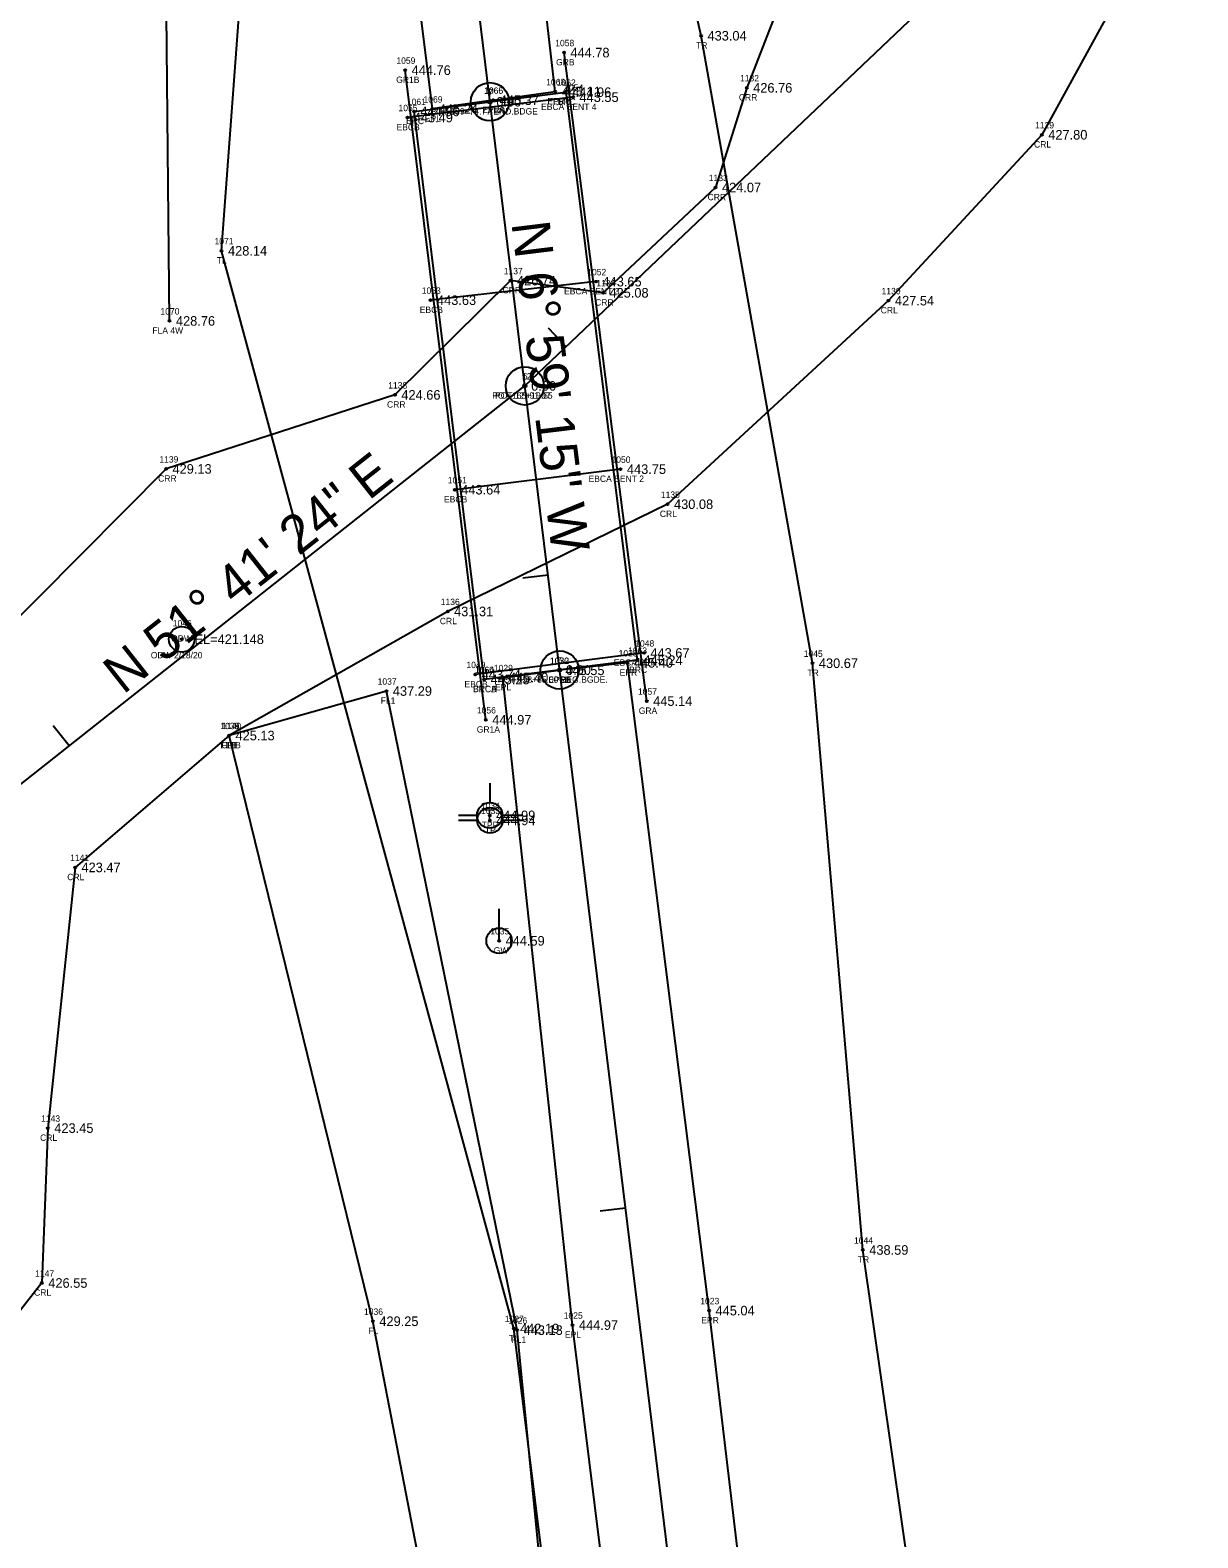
# Model space of a CAD drawing. Extents: x 1858454 to 1858924, y 1147053 to 1148170.
# Drawn here: x 1858606.4 to 1858789.5, y 1147434.7 to 1147671.2 of the extents above; entities that cross this region are included whole.
import ezdxf

# ---------------------------------------------------------------- set-up
doc = ezdxf.new("R2010")
doc.units = 0
for name, color, linetype in [('RD_EX_Bridge', 7, 'Continuous'), ('RD_EX_Bridge_txCode', 7, 'Continuous'), ('RD_EX_Fence_Other', 7, 'Continuous'), ('RD_EX_Fence_Other_txCode', 7, 'Continuous'), ('RD_EX_GuardRail', 7, 'Continuous'), ('RD_EX_GuardRail_txCode', 7, 'Continuous'), ('RD_EX_H2O', 7, 'Continuous'), ('RD_EX_H2O_txCode', 7, 'Continuous'), ('RD_EX_Road', 7, 'Continuous'), ('RD_EX_Road_txCode', 7, 'Continuous'), ('RD_EX_TX_Bridge_ELEV', 7, 'Continuous'), ('RD_EX_TX_Fence_Other_ELEV', 7, 'Continuous'), ('RD_EX_TX_GuardRail_ELEV', 7, 'Continuous'), ('RD_EX_TX_H2O_ELEV', 7, 'Continuous'), ('RD_EX_TX_Road_ELEV', 7, 'Continuous'), ('RD_EX_TX_UT_ELEV', 7, 'Continuous'), ('RD_EX_TX_VEG_ELEV', 7, 'Continuous'), ('RD_EX_UT', 7, 'Continuous'), ('RD_EX_UT_txCode', 7, 'Continuous'), ('RD_EX_VEG', 7, 'Continuous'), ('RD_EX_VEG_txCode', 7, 'Continuous'), ('RD_HC_Cl', 7, 'Continuous'), ('RD_HC_Data', 7, 'Continuous'), ('RD_HC_Data_Tic', 7, 'Continuous'), ('RD_HC_Survey_ELEV', 7, 'Continuous'), ('RD_HC_txCode', 7, 'Continuous'), ('RD_SMD_Locator', 7, 'Continuous')]:
    doc.layers.add(name, color=color, linetype=linetype)

msp = doc.modelspace()

# ---------------------------------------------------------------- linework, layer by layer
at = {"layer": 'RD_EX_Bridge'}
for p, q in [((1858691.53, 1147660.66), (1858665.55, 1147657.47)), ((1858695.14, 1147631.74), (1858669.19, 1147628.83)), ((1858698.97, 1147602.33), (1858672.99, 1147599.11)), ((1858702.65, 1147573.51), (1858676.2, 1147570.13))]:
    msp.add_line(p, q, dxfattribs=at)
msp.add_lwpolyline([(1858677.59, 1147569.36), (1858666.6, 1147658.44), (1858690.38, 1147661.45), (1858701.56, 1147572.37), (1858677.59, 1147569.35)], dxfattribs=at)
at = {"layer": 'RD_EX_Fence_Other'}
for points in [[(1858628.27, 1147625.58), (1858627.01, 1147754.05), (1858615.95, 1147851.08), (1858606.98, 1147957.76), (1858595.17, 1148052.68), (1858581.78, 1148154.12)], [(1858680.85, 1147361.22), (1858692.48, 1147368.01), (1858682.77, 1147467.32), (1858662.27, 1147567.54), (1858637.61, 1147560.56)], [(1858724.59, 1147070.61), (1858704.63, 1147165.53), (1858685.01, 1147263.02), (1858674.78, 1147319.72), (1858680.95, 1147360.94), (1858660.16, 1147468.71), (1858637.61, 1147560.56)]]:
    msp.add_lwpolyline(points, dxfattribs=at)
at = {"layer": 'RD_EX_GuardRail'}
for p, q in [((1858703.08, 1147565.96), (1858690.11, 1147667.66)), ((1858677.86, 1147563.02), (1858665.22, 1147664.9))]:
    msp.add_line(p, q, dxfattribs=at)
at = {"layer": 'RD_EX_H2O'}
for points in [[(1858879.83, 1148102.54), (1858871.42, 1148034.27), (1858866.93, 1147971.73), (1858863.21, 1147909.44), (1858860.9, 1147860.04), (1858873.82, 1147825.54), (1858891.79, 1147781.55), (1858894.95, 1147773.07), (1858887.01, 1147735.25), (1858825.08, 1147733.03), (1858791.14, 1147702.41), (1858765.02, 1147654.77), (1858740.99, 1147628.76), (1858706.35, 1147596.83), (1858671.87, 1147580.02), (1858637.61, 1147560.56), (1858613.46, 1147539.88), (1858609.2, 1147499), (1858608.26, 1147474.71), (1858583.43, 1147442.99), (1858542.68, 1147417.32), (1858497.34, 1147430.55)], [(1858842, 1147848.22), (1858847.52, 1147794.04), (1858841.16, 1147786.48), (1858816.23, 1147769.28), (1858759.58, 1147742.8), (1858751.47, 1147732.35), (1858731.2, 1147689.66), (1858724.77, 1147677.64), (1858718.76, 1147662.14), (1858713.87, 1147646.5), (1858696.23, 1147629.99), (1858681.73, 1147631.9), (1858663.61, 1147613.98), (1858627.73, 1147602.37), (1858587.46, 1147561.81), (1858570.79, 1147529.07), (1858577.35, 1147512.16), (1858564.18, 1147528.65), (1858536.5, 1147564.8), (1858503.8, 1147609.24)]]:
    msp.add_lwpolyline(points, dxfattribs=at)
for radius in [2, 0.15]:
    msp.add_circle((1858630.18, 1147575.66), radius, dxfattribs=at)
at = {"layer": 'RD_EX_Road'}
for points in [[(1858679.02, 1147660.19), (1858688.73, 1147661.54), (1858677.21, 1147761.6), (1858664.75, 1147860.38), (1858652.33, 1147959.9), (1858640.18, 1148058.71), (1858627.63, 1148158.94)], [(1858679.02, 1147660.19), (1858669.49, 1147658.82), (1858657, 1147758.92), (1858643.96, 1147857.84), (1858631.87, 1147958), (1858619.69, 1148055.49), (1858606.59, 1148156.75)], [(1858739.58, 1147072.32), (1858726.74, 1147170.58), (1858715.7, 1147269.68), (1858703.76, 1147368.69), (1858691.45, 1147468.11), (1858680.5, 1147569.65), (1858689.32, 1147570.79)], [(1858760.33, 1147074.17), (1858747.61, 1147172.63), (1858736.08, 1147271.97), (1858724.51, 1147372.2), (1858712.86, 1147470.38), (1858700.06, 1147571.96), (1858689.32, 1147570.79)]]:
    msp.add_lwpolyline(points, dxfattribs=at)
at = {"layer": 'RD_EX_UT'}
for p, q in [((1858678.47, 1147553.11), (1858678.47, 1147550.04)), ((1858673.54, 1147548.06), (1858676.47, 1147548.06)), ((1858673.57, 1147547.27), (1858676.5, 1147547.27)), ((1858680.47, 1147548.06), (1858683.54, 1147548.06)), ((1858680.5, 1147547.27), (1858683.57, 1147547.27)), ((1858679.94, 1147528.37), (1858679.94, 1147533.37))]:
    msp.add_line(p, q, dxfattribs=at)
for centre in [(1858678.47, 1147548.04), (1858678.5, 1147547.25), (1858679.94, 1147528.37)]:
    msp.add_circle(centre, 2, dxfattribs=at)
at = {"layer": 'RD_EX_VEG'}
for points in [[(1858786.58, 1147073.62), (1858775.98, 1147174.64), (1858762.89, 1147274.03), (1858752.24, 1147373.24), (1858736.96, 1147479.89), (1858729.06, 1147571.9), (1858711.6, 1147670.3), (1858690.41, 1147764.38), (1858680.89, 1147862.43), (1858668.42, 1147961.01), (1858651.26, 1148061.01), (1858641.53, 1148160.37)], [(1858726.29, 1147071.02), (1858708.41, 1147166.41), (1858698.92, 1147264.27), (1858694.52, 1147368.74), (1858682.22, 1147467.57), (1858636.43, 1147636.58), (1858645.41, 1147757.54), (1858631.11, 1147856.08), (1858618.46, 1147956.68), (1858606.82, 1148055.62), (1858592.91, 1148154.69)]]:
    msp.add_lwpolyline(points, dxfattribs=at)
at = {"layer": 'RD_HC_Cl'}
for p, q in [((1858750.25, 1147074.55), (1858617.68, 1148156.23)), ((1858683.96, 1147615.39), (1858865, 1147787.44)), ((1858601.42, 1147550.17), (1858683.96, 1147615.39))]:
    msp.add_line(p, q, dxfattribs=at)
at = {"layer": 'RD_HC_Data'}
for centre, radius in [((1858678.5, 1147659.95), 3), ((1858678.5, 1147659.95), 0.282), ((1858683.96, 1147615.39), 3), ((1858683.96, 1147615.39), 3), ((1858683.96, 1147615.39), 0.282), ((1858683.96, 1147615.39), 0.282), ((1858689.42, 1147570.84), 3), ((1858689.42, 1147570.84), 0.282)]:
    msp.add_circle(centre, radius, dxfattribs=at)
at = {"layer": 'RD_HC_Data_Tic'}
for p, q in [((1858690.44, 1147621.54), (1858687.68, 1147624.44)), ((1858687.6, 1147585.73), (1858683.63, 1147585.24)), ((1858612.51, 1147558.93), (1858610.03, 1147562.07)), ((1858699.77, 1147486.47), (1858695.8, 1147485.98))]:
    msp.add_line(p, q, dxfattribs=at)
at = {"layer": 'RD_SMD_Locator'}
for centre in [(1858711.6, 1147670.3), (1858690.11, 1147667.66), (1858665.22, 1147664.9), (1858718.76, 1147662.14), (1858678.5, 1147659.95), (1858679.02, 1147660.19), (1858679.02, 1147660.19), (1858688.73, 1147661.54), (1858690.38, 1147661.45), (1858691.53, 1147660.66), (1858665.55, 1147657.47), (1858666.6, 1147658.44), (1858669.49, 1147658.82), (1858765.02, 1147654.77), (1858713.87, 1147646.5), (1858636.43, 1147636.58), (1858681.73, 1147631.9), (1858695.14, 1147631.74), (1858669.19, 1147628.83), (1858696.23, 1147629.99), (1858740.99, 1147628.76), (1858628.27, 1147625.58), (1858683.96, 1147615.39), (1858683.96, 1147615.39), (1858663.61, 1147613.98), (1858627.73, 1147602.37), (1858698.97, 1147602.33), (1858672.99, 1147599.11), (1858706.35, 1147596.83), (1858671.87, 1147580.02), (1858700.06, 1147571.96), (1858701.56, 1147572.37), (1858702.65, 1147573.51), (1858676.2, 1147570.13), (1858680.5, 1147569.65), (1858689.32, 1147570.79), (1858689.32, 1147570.79), (1858689.42, 1147570.84), (1858729.06, 1147571.9), (1858662.27, 1147567.54), (1858677.59, 1147569.36), (1858677.59, 1147569.35), (1858703.08, 1147565.96), (1858677.86, 1147563.02), (1858637.61, 1147560.56), (1858637.61, 1147560.56), (1858637.61, 1147560.56), (1858678.47, 1147548.04), (1858678.5, 1147547.25), (1858613.46, 1147539.88), (1858679.94, 1147528.37), (1858609.2, 1147499), (1858736.96, 1147479.89), (1858608.26, 1147474.71), (1858712.86, 1147470.38), (1858660.16, 1147468.71), (1858691.45, 1147468.11), (1858682.22, 1147467.57), (1858682.77, 1147467.32)]:
    msp.add_circle(centre, 0.15, dxfattribs=at)

# ---------------------------------------------------------------- texts
at = {"layer": 'RD_EX_Bridge_txCode'}
for s, p in [('1062', (1858688.97, 1147662.45)), ('1054', (1858690.15, 1147661.66)), ('1061', (1858665.47, 1147659.44)), ('EBCA BENT 4', (1858686.51, 1147658.66)), ('BRC', (1858689.13, 1147659.45)), ('1055', (1858664.16, 1147658.47)), ('BRC', (1858665.35, 1147656.44)), ('EBCB', (1858663.85, 1147655.47)), ('1052', (1858693.75, 1147632.74)), ('1053', (1858667.81, 1147629.83)), ('EBCA BENT 3', (1858690.11, 1147629.74)), ('EBCB', (1858667.49, 1147626.83)), ('1050', (1858697.55, 1147603.33)), ('1051', (1858671.89, 1147600.11)), ('EBCA BENT 2', (1858693.95, 1147600.33)), ('EBCB', (1858671.29, 1147597.11)), ('1048', (1858701.27, 1147574.51)), ('1049', (1858674.81, 1147571.13)), ('EBCA BENT 1', (1858697.91, 1147571.51)), ('1063', (1858700.15, 1147573.37)), ('1060', (1858676.14, 1147570.36)), ('1064', (1858676.18, 1147570.35)), ('BRC', (1858700.31, 1147570.37)), ('EBCB', (1858674.5, 1147568.13)), ('BRCA', (1858675.85, 1147567.36)), ('BRCB', (1858675.86, 1147567.35))]:
    msp.add_text(s, height=1, dxfattribs=at).set_placement(p)
at = {"layer": 'RD_EX_Fence_Other_txCode'}
for s, p in [('1070', (1858626.84, 1147626.58)), ('FLA 4W', (1858625.57, 1147623.58)), ('1037', (1858660.89, 1147568.54)), ('FL1', (1858661.37, 1147565.54)), ('1038', (1858636.23, 1147561.56)), ('1039', (1858636.23, 1147561.56)), ('FL1B', (1858636.24, 1147558.56)), ('FLB', (1858636.41, 1147558.56)), ('1036', (1858658.75, 1147469.71)), ('1026', (1858681.36, 1147468.32)), ('FL', (1858659.43, 1147466.71)), ('FL1', (1858681.87, 1147465.32))]:
    msp.add_text(s, height=1, dxfattribs=at).set_placement(p)
at = {"layer": 'RD_EX_GuardRail_txCode'}
for s, p in [('1058', (1858688.73, 1147668.66)), ('1059', (1858663.83, 1147665.9)), ('GRB', (1858688.86, 1147665.66)), ('GR1B', (1858663.8, 1147662.9)), ('1057', (1858701.7, 1147566.96)), ('1056', (1858676.45, 1147564.02)), ('GRA', (1858701.82, 1147563.96)), ('GR1A', (1858676.43, 1147561.02))]:
    msp.add_text(s, height=1, dxfattribs=at).set_placement(p)
at = {"layer": 'RD_EX_H2O'}
msp.add_text('ODW', height=1, dxfattribs=at).set_placement((1858628.51, 1147575.29))
at = {"layer": 'RD_EX_H2O_txCode'}
for s, p in [('1132', (1858717.7, 1147663.14)), ('CRR', (1858717.51, 1147660.14)), ('1129', (1858763.95, 1147655.77)), ('CRL', (1858763.79, 1147652.77)), ('1133', (1858712.81, 1147647.5)), ('CRR', (1858712.62, 1147644.5)), ('1137', (1858680.66, 1147632.9)), ('1134', (1858695.17, 1147630.99)), ('CRR', (1858680.47, 1147629.9)), ('CRR', (1858694.98, 1147627.99)), ('1130', (1858739.89, 1147629.76)), ('CRL', (1858739.76, 1147626.76)), ('1138', (1858662.55, 1147614.98)), ('CRR', (1858662.36, 1147611.98)), ('1139', (1858626.67, 1147603.37)), ('CRR', (1858626.48, 1147600.37)), ('1135', (1858705.29, 1147597.83)), ('CRL', (1858705.13, 1147594.83)), ('1136', (1858670.78, 1147581.02)), ('1046', (1858628.77, 1147577.66)), ('CRL', (1858670.64, 1147578.02)), ('ODW 2/18/20', (1858625.33, 1147572.66)), ('1140', (1858636.51, 1147561.56)), ('CRL', (1858636.39, 1147558.56)), ('1141', (1858612.68, 1147540.88)), ('CRL', (1858612.23, 1147537.88)), ('1143', (1858608.13, 1147500)), ('CRL', (1858607.97, 1147497)), ('1147', (1858607.2, 1147475.71)), ('CRL', (1858607.03, 1147472.71))]:
    msp.add_text(s, height=1, dxfattribs=at).set_placement(p)
at = {"layer": 'RD_EX_Road_txCode'}
for s, p in [('1066', (1858677.58, 1147661.19)), ('1065', (1858677.61, 1147661.19)), ('1068', (1858687.32, 1147662.54)), ('1069', (1858668.08, 1147659.82)), ('EPR', (1858687.5, 1147659.54)), ('EPL', (1858668.28, 1147656.82)), ('EPRA', (1858677.3, 1147658.19)), ('EPLA', (1858677.32, 1147658.19)), ('1030', (1858687.89, 1147571.79)), ('1032', (1858687.93, 1147571.79)), ('1028', (1858698.67, 1147572.96)), ('1029', (1858679.11, 1147570.65)), ('EPRB', (1858687.62, 1147568.79)), ('EPLB', (1858687.64, 1147568.79)), ('EPR', (1858698.83, 1147569.96)), ('EPL', (1858679.29, 1147567.65)), ('1023', (1858711.47, 1147471.38)), ('1025', (1858690.06, 1147469.11)), ('EPR', (1858711.63, 1147468.38)), ('EPL', (1858690.25, 1147466.11))]:
    msp.add_text(s, height=1, dxfattribs=at).set_placement(p)
at = {"layer": 'RD_EX_TX_Bridge_ELEV'}
for s, p in [('444.96', (1858691.38, 1147660.7)), ('443.55', (1858692.53, 1147659.91)), ('443.49', (1858666.55, 1147656.72)), ('444.96', (1858667.6, 1147657.69)), ('443.65', (1858696.14, 1147630.99)), ('443.63', (1858670.19, 1147628.08)), ('443.75', (1858699.97, 1147601.58)), ('443.64', (1858673.99, 1147598.36)), ('445.24', (1858702.56, 1147571.62)), ('443.67', (1858703.65, 1147572.76)), ('443.74', (1858677.2, 1147569.38)), ('445.25', (1858678.59, 1147568.61)), ('445.25', (1858678.59, 1147568.6))]:
    msp.add_text(s, height=1.5, dxfattribs=at).set_placement(p)
at = {"layer": 'RD_EX_TX_Fence_Other_ELEV'}
for s, p in [('428.76', (1858629.27, 1147624.83)), ('437.29', (1858663.27, 1147566.79)), ('425.13', (1858638.61, 1147559.81)), ('425.13', (1858638.61, 1147559.81)), ('429.25', (1858661.16, 1147467.96)), ('443.13', (1858683.77, 1147466.57))]:
    msp.add_text(s, height=1.5, dxfattribs=at).set_placement(p)
at = {"layer": 'RD_EX_TX_GuardRail_ELEV'}
for s, p in [('444.78', (1858691.11, 1147666.91)), ('444.76', (1858666.22, 1147664.15)), ('445.14', (1858704.08, 1147565.21)), ('444.97', (1858678.86, 1147562.27))]:
    msp.add_text(s, height=1.5, dxfattribs=at).set_placement(p)
at = {"layer": 'RD_EX_TX_H2O_ELEV'}
for s, p in [('426.76', (1858719.76, 1147661.39)), ('427.80', (1858766.02, 1147654.02)), ('424.07', (1858714.87, 1147645.75)), ('426.74', (1858682.73, 1147631.15)), ('425.08', (1858697.23, 1147629.24)), ('427.54', (1858741.99, 1147628.01)), ('424.66', (1858664.61, 1147613.23)), ('429.13', (1858628.73, 1147601.62)), ('430.08', (1858707.35, 1147596.08)), ('431.31', (1858672.87, 1147579.27)), ('EL=421.148', (1858632.18, 1147574.91)), ('425.13', (1858638.61, 1147559.81)), ('423.47', (1858614.46, 1147539.13)), ('423.45', (1858610.2, 1147498.25)), ('426.55', (1858609.26, 1147473.96))]:
    msp.add_text(s, height=1.5, dxfattribs=at).set_placement(p)
at = {"layer": 'RD_EX_TX_Road_ELEV'}
for s, p in [('445.11', (1858689.73, 1147660.79)), ('445.24', (1858670.49, 1147658.07)), ('445.37', (1858680.02, 1147659.44)), ('445.37', (1858680.02, 1147659.44)), ('445.40', (1858701.06, 1147571.21)), ('445.40', (1858681.5, 1147568.9)), ('445.55', (1858690.32, 1147570.04)), ('445.55', (1858690.32, 1147570.04)), ('445.04', (1858713.86, 1147469.63)), ('444.97', (1858692.45, 1147467.36))]:
    msp.add_text(s, height=1.5, dxfattribs=at).set_placement(p)
at = {"layer": 'RD_EX_TX_UT_ELEV'}
for s, p in [('444.99', (1858679.47, 1147547.29)), ('444.94', (1858679.5, 1147546.5)), ('444.59', (1858680.94, 1147527.62))]:
    msp.add_text(s, height=1.5, dxfattribs=at).set_placement(p)
at = {"layer": 'RD_EX_TX_VEG_ELEV'}
for s, p in [('433.04', (1858712.6, 1147669.55)), ('428.14', (1858637.43, 1147635.83)), ('430.67', (1858730.06, 1147571.15)), ('438.59', (1858737.96, 1147479.14)), ('442.19', (1858683.22, 1147466.82))]:
    msp.add_text(s, height=1.5, dxfattribs=at).set_placement(p)
at = {"layer": 'RD_EX_UT'}
msp.add_text('T', height=2, dxfattribs=at).set_placement((1858677.62, 1147546.99))
at = {"layer": 'RD_EX_UT_txCode'}
for s, p in [('1034', (1858677.08, 1147549.04)), ('1033', (1858677.11, 1147548.25)), ('TPP', (1858677.2, 1147546.04)), ('TP', (1858677.7, 1147545.25)), ('1035', (1858678.55, 1147529.37)), ('GW', (1858679.09, 1147526.37))]:
    msp.add_text(s, height=1, dxfattribs=at).set_placement(p)
at = {"layer": 'RD_EX_VEG_txCode'}
for s, p in [('TR', (1858710.81, 1147668.3)), ('1071', (1858635.32, 1147637.58)), ('TL', (1858635.65, 1147634.58)), ('1045', (1858727.68, 1147572.9)), ('TR', (1858728.27, 1147569.9)), ('1044', (1858735.57, 1147480.89)), ('TR', (1858736.16, 1147477.89)), ('1027', (1858680.83, 1147468.57)), ('TL', (1858681.45, 1147465.57))]:
    msp.add_text(s, height=1, dxfattribs=at).set_placement(p)
at = {"layer": 'RD_HC_Data'}
for s, rotation, p in [('N 6%%d 59\' 15" W', 276.9874, (1858681.85, 1147640.91)), ('N 51%%d 41\' 24" E', 38.31, (1858621, 1147566.91))]:
    msp.add_text(s, height=6, rotation=rotation, dxfattribs=at).set_placement(p)
at = {"layer": 'RD_HC_Survey_ELEV'}
for p in [(1858679.5, 1147659.2), (1858684.96, 1147614.64), (1858684.96, 1147614.64), (1858690.42, 1147570.09)]:
    msp.add_text('0.00', height=1.5, dxfattribs=at).set_placement(p)
at = {"layer": 'RD_HC_txCode'}
for s, p in [('7', (1858678.22, 1147660.95)), ('POT 159+74.77 END.BDGE', (1858669.17, 1147657.95)), ('12', (1858683.52, 1147616.39)), ('6', (1858683.66, 1147616.39)), ('POT 165+19.65', (1858678.84, 1147613.39)), ('POT 12+91.07', (1858679.29, 1147613.39)), ('5', (1858689.14, 1147571.84)), ('POT 158+85.00 BEG.BGDE.', (1858679.75, 1147568.84))]:
    msp.add_text(s, height=1, dxfattribs=at).set_placement(p)

doc.saveas('drawing.dxf')
